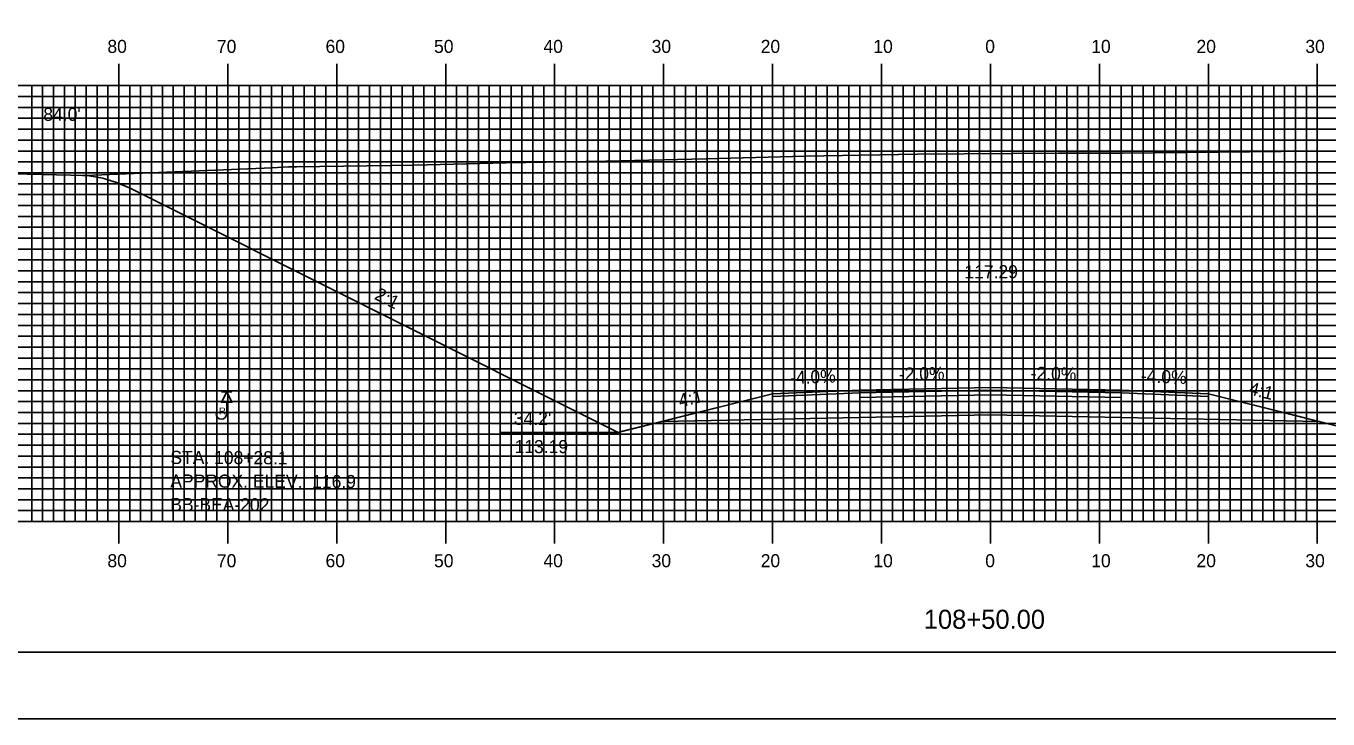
# Model space of a CAD drawing. Extents: x 1768874 to 1769217, y 442591 to 442811.
# Drawn here: x 1768951.5 to 1769071, y 442590.5 to 442654.1 of the extents above; entities that cross this region are included whole.
import ezdxf

# ---------------------------------------------------------------- set-up
doc = ezdxf.new("R2010")
doc.units = 0
for name, color, linetype in [('ANNOTATION', 7, 'Continuous'), ('BORDER', 7, 'Continuous'), ('BORING - REFUSAL', 7, 'Continuous'), ('D_Roadway_Centerline', 7, 'Continuous'), ('D_Roadway_Centerline_Text', 7, 'Continuous'), ('D_Roadway_Edge_Shoulder', 7, 'Continuous'), ('D_Roadway_Edge_TW', 7, 'Continuous'), ('D_Roadway_Pavement', 7, 'Continuous'), ('D_Roadway_SlopeLines', 7, 'Continuous'), ('D_Roadway_SubGrade', 7, 'Continuous'), ('D_Text_Standard', 7, 'Continuous'), ('H_V ANNOTATION', 7, 'Continuous'), ('MAJOR', 7, 'Continuous'), ('MINOR', 7, 'Continuous'), ('PDRAIN', 7, 'Continuous'), ('PLOT BOUNDARY', 7, 'Continuous'), ('S_Roadway_Centerline', 7, 'Continuous')]:
    doc.layers.add(name, color=color, linetype=linetype)

msp = doc.modelspace()

# ---------------------------------------------------------------- linework, layer by layer
at = {"layer": 'BORDER'}
msp.add_lwpolyline([(1768890.39, 442596.67), (1769210.39, 442596.67), (1769210.39, 442806.67), (1768890.39, 442806.67)], close=True, dxfattribs=at)
at = {"layer": 'BORING - REFUSAL'}
for p, q in [((1768970.37, 442620.57), (1768969.41, 442620.57)), ((1768969.89, 442619.61), (1768969.89, 442618.55))]:
    msp.add_line(p, q, dxfattribs=at)
msp.add_lwpolyline([(1768969.89, 442620.57), (1768970.37, 442619.61), (1768969.41, 442619.61)], close=True, dxfattribs=at)
msp.add_arc((1768969.4, 442618.55), 0.485, 180, 0, dxfattribs=at)
at = {"layer": 'D_Roadway_Centerline'}
msp.add_lwpolyline([(1768956.02, 442640.45), (1768957.27, 442640.39), (1768957.99, 442640.27), (1768958.52, 442640.17), (1768959.57, 442639.85), (1768959.77, 442639.79), (1768959.88, 442639.75), (1768961.02, 442639.25), (1768961.03, 442639.25), (1769005.82, 442616.85), (1769005.98, 442616.89), (1769009.81, 442617.85), (1769019.99, 442620.4), (1769027.99, 442620.72), (1769039.99, 442620.96), (1769051.99, 442620.72), (1769051.99, 442620.72), (1769051.99, 442620.72), (1769059.99, 442620.4), (1769059.99, 442620.4), (1769068.24, 442618.33), (1769070.16, 442617.85), (1769072.1, 442617.37)], dxfattribs=at)
at = {"layer": 'D_Roadway_Edge_Shoulder'}
for points in [[(1769027.99, 442620.72), (1769019.99, 442620.4), (1769019.99, 442620.15), (1769027.99, 442620.47)], [(1769051.99, 442620.72), (1769059.99, 442620.4), (1769059.99, 442620.15), (1769051.99, 442620.47)]]:
    msp.add_lwpolyline(points, close=True, dxfattribs=at)
at = {"layer": 'D_Roadway_Edge_TW'}
msp.add_lwpolyline([(1769027.99, 442620.47), (1769027.99, 442620.72), (1769039.99, 442620.96), (1769051.99, 442620.72), (1769051.99, 442620.47), (1769039.99, 442620.71)], close=True, dxfattribs=at)
at = {"layer": 'D_Roadway_Pavement'}
msp.add_lwpolyline([(1769027.99, 442620.05), (1769027.99, 442620.47), (1769039.99, 442620.71), (1769051.99, 442620.47), (1769051.99, 442620.05), (1769039.99, 442620.29)], close=True, dxfattribs=at)
at = {"layer": 'D_Roadway_SlopeLines'}
for points in [[(1769005.82, 442616.85), (1768961.02, 442639.25), (1768959.77, 442639.79), (1768958.52, 442640.17), (1768957.27, 442640.39), (1768956.02, 442640.45)], [(1769019.99, 442620.4), (1769005.82, 442616.85)], [(1769059.99, 442620.4), (1769074.16, 442616.85)]]:
    msp.add_lwpolyline(points, dxfattribs=at)
at = {"layer": 'D_Roadway_SubGrade'}
msp.add_lwpolyline([(1769027.99, 442618.22), (1769009.81, 442617.85), (1769019.99, 442620.4), (1769019.99, 442620.15), (1769027.99, 442620.47), (1769039.99, 442620.71), (1769051.99, 442620.47), (1769059.99, 442620.15), (1769059.99, 442620.4), (1769070.16, 442617.85), (1769051.99, 442618.22), (1769039.99, 442618.46)], close=True, dxfattribs=at)
at = {"layer": 'MAJOR'}
for p, q in [((1768959.99, 442650.67), (1768959.99, 442648.67)), ((1768969.99, 442650.67), (1768969.99, 442648.67)), ((1768979.99, 442650.67), (1768979.99, 442648.67)), ((1768989.99, 442650.67), (1768989.99, 442648.67)), ((1768999.99, 442650.67), (1768999.99, 442648.67)), ((1769009.99, 442650.67), (1769009.99, 442648.67)), ((1769019.99, 442650.67), (1769019.99, 442648.67)), ((1769029.99, 442650.67), (1769029.99, 442648.67)), ((1769039.99, 442650.67), (1769039.99, 442648.67)), ((1769049.99, 442650.67), (1769049.99, 442648.67)), ((1769059.99, 442650.67), (1769059.99, 442648.67)), ((1769069.99, 442650.67), (1769069.99, 442648.67)), ((1768899.99, 442648.67), (1769179.99, 442648.67)), ((1768899.99, 442648.67), (1769179.99, 442648.67)), ((1768959.99, 442608.67), (1768959.99, 442648.67)), ((1768969.99, 442608.67), (1768969.99, 442648.67)), ((1768979.99, 442608.67), (1768979.99, 442648.67)), ((1768989.99, 442608.67), (1768989.99, 442648.67)), ((1768999.99, 442608.67), (1768999.99, 442648.67)), ((1769009.99, 442608.67), (1769009.99, 442648.67)), ((1769019.99, 442608.67), (1769019.99, 442648.67)), ((1769029.99, 442608.67), (1769029.99, 442648.67)), ((1769039.99, 442608.67), (1769039.99, 442648.67)), ((1769049.99, 442608.67), (1769049.99, 442648.67)), ((1769059.99, 442608.67), (1769059.99, 442648.67)), ((1769069.99, 442608.67), (1769069.99, 442648.67)), ((1768899.99, 442643.67), (1769179.99, 442643.67)), ((1768899.99, 442638.67), (1769179.99, 442638.67)), ((1768899.99, 442633.67), (1769179.99, 442633.67)), ((1768899.99, 442628.67), (1769179.99, 442628.67)), ((1768899.99, 442623.67), (1769179.99, 442623.67)), ((1768899.99, 442618.67), (1769179.99, 442618.67)), ((1768899.99, 442613.67), (1769179.99, 442613.67)), ((1768899.99, 442608.67), (1769179.99, 442608.67)), ((1768899.99, 442608.67), (1769179.99, 442608.67)), ((1768959.99, 442606.66), (1768959.99, 442608.67)), ((1768969.99, 442606.66), (1768969.99, 442608.67)), ((1768979.99, 442606.66), (1768979.99, 442608.67)), ((1768989.99, 442606.66), (1768989.99, 442608.67)), ((1768999.99, 442606.66), (1768999.99, 442608.67)), ((1769009.99, 442606.66), (1769009.99, 442608.67)), ((1769019.99, 442606.66), (1769019.99, 442608.67)), ((1769029.99, 442606.66), (1769029.99, 442608.67)), ((1769039.99, 442606.66), (1769039.99, 442608.67)), ((1769049.99, 442606.66), (1769049.99, 442608.67)), ((1769059.99, 442606.66), (1769059.99, 442608.67)), ((1769069.99, 442606.66), (1769069.99, 442608.67))]:
    msp.add_line(p, q, dxfattribs=at)
at = {"layer": 'MINOR'}
for p, q in [((1768951.99, 442608.67), (1768951.99, 442648.67)), ((1768952.99, 442608.67), (1768952.99, 442648.67)), ((1768953.99, 442608.67), (1768953.99, 442648.67)), ((1768954.99, 442608.67), (1768954.99, 442648.67)), ((1768955.99, 442608.67), (1768955.99, 442648.67)), ((1768956.99, 442608.67), (1768956.99, 442648.67)), ((1768957.99, 442608.67), (1768957.99, 442648.67)), ((1768958.99, 442608.67), (1768958.99, 442648.67)), ((1768960.99, 442608.67), (1768960.99, 442648.67)), ((1768961.99, 442608.67), (1768961.99, 442648.67)), ((1768962.99, 442608.67), (1768962.99, 442648.67)), ((1768963.99, 442608.67), (1768963.99, 442648.67)), ((1768964.99, 442608.67), (1768964.99, 442648.67)), ((1768965.99, 442608.67), (1768965.99, 442648.67)), ((1768966.99, 442608.67), (1768966.99, 442648.67)), ((1768967.99, 442608.67), (1768967.99, 442648.67)), ((1768968.99, 442608.67), (1768968.99, 442648.67)), ((1768970.99, 442608.67), (1768970.99, 442648.67)), ((1768971.99, 442608.67), (1768971.99, 442648.67)), ((1768972.99, 442608.67), (1768972.99, 442648.67)), ((1768973.99, 442608.67), (1768973.99, 442648.67)), ((1768974.99, 442608.67), (1768974.99, 442648.67)), ((1768975.99, 442608.67), (1768975.99, 442648.67)), ((1768976.99, 442608.67), (1768976.99, 442648.67)), ((1768977.99, 442608.67), (1768977.99, 442648.67)), ((1768978.99, 442608.67), (1768978.99, 442648.67)), ((1768980.99, 442608.67), (1768980.99, 442648.67)), ((1768981.99, 442608.67), (1768981.99, 442648.67)), ((1768982.99, 442608.67), (1768982.99, 442648.67)), ((1768983.99, 442608.67), (1768983.99, 442648.67)), ((1768984.99, 442608.67), (1768984.99, 442648.67)), ((1768985.99, 442608.67), (1768985.99, 442648.67)), ((1768986.99, 442608.67), (1768986.99, 442648.67)), ((1768987.99, 442608.67), (1768987.99, 442648.67)), ((1768988.99, 442608.67), (1768988.99, 442648.67)), ((1768990.99, 442608.67), (1768990.99, 442648.67)), ((1768991.99, 442608.67), (1768991.99, 442648.67)), ((1768992.99, 442608.67), (1768992.99, 442648.67)), ((1768993.99, 442608.67), (1768993.99, 442648.67)), ((1768994.99, 442608.67), (1768994.99, 442648.67)), ((1768995.99, 442608.67), (1768995.99, 442648.67)), ((1768996.99, 442608.67), (1768996.99, 442648.67)), ((1768997.99, 442608.67), (1768997.99, 442648.67)), ((1768998.99, 442608.67), (1768998.99, 442648.67)), ((1769000.99, 442608.67), (1769000.99, 442648.67)), ((1769001.99, 442608.67), (1769001.99, 442648.67)), ((1769002.99, 442608.67), (1769002.99, 442648.67)), ((1769003.99, 442608.67), (1769003.99, 442648.67)), ((1769004.99, 442608.67), (1769004.99, 442648.67)), ((1769005.99, 442608.67), (1769005.99, 442648.67)), ((1769006.99, 442608.67), (1769006.99, 442648.67)), ((1769007.99, 442608.67), (1769007.99, 442648.67)), ((1769008.99, 442608.67), (1769008.99, 442648.67)), ((1769010.99, 442608.67), (1769010.99, 442648.67)), ((1769011.99, 442608.67), (1769011.99, 442648.67)), ((1769012.99, 442608.67), (1769012.99, 442648.67)), ((1769013.99, 442608.67), (1769013.99, 442648.67)), ((1769014.99, 442608.67), (1769014.99, 442648.67)), ((1769015.99, 442608.67), (1769015.99, 442648.67)), ((1769016.99, 442608.67), (1769016.99, 442648.67)), ((1769017.99, 442608.67), (1769017.99, 442648.67)), ((1769018.99, 442608.67), (1769018.99, 442648.67)), ((1769020.99, 442608.67), (1769020.99, 442648.67)), ((1769021.99, 442608.67), (1769021.99, 442648.67)), ((1769022.99, 442608.67), (1769022.99, 442648.67)), ((1769023.99, 442608.67), (1769023.99, 442648.67)), ((1769024.99, 442608.67), (1769024.99, 442648.67)), ((1769025.99, 442608.67), (1769025.99, 442648.67)), ((1769026.99, 442608.67), (1769026.99, 442648.67)), ((1769027.99, 442608.67), (1769027.99, 442648.67)), ((1769028.99, 442608.67), (1769028.99, 442648.67)), ((1769030.99, 442608.67), (1769030.99, 442648.67)), ((1769031.99, 442608.67), (1769031.99, 442648.67)), ((1769032.99, 442608.67), (1769032.99, 442648.67)), ((1769033.99, 442608.67), (1769033.99, 442648.67)), ((1769034.99, 442608.67), (1769034.99, 442648.67)), ((1769035.99, 442608.67), (1769035.99, 442648.67)), ((1769036.99, 442608.67), (1769036.99, 442648.67)), ((1769037.99, 442608.67), (1769037.99, 442648.67)), ((1769038.99, 442608.67), (1769038.99, 442648.67)), ((1769040.99, 442608.67), (1769040.99, 442648.67)), ((1769041.99, 442608.67), (1769041.99, 442648.67)), ((1769042.99, 442608.67), (1769042.99, 442648.67)), ((1769043.99, 442608.67), (1769043.99, 442648.67)), ((1769044.99, 442608.67), (1769044.99, 442648.67)), ((1769045.99, 442608.67), (1769045.99, 442648.67)), ((1769046.99, 442608.67), (1769046.99, 442648.67)), ((1769047.99, 442608.67), (1769047.99, 442648.67)), ((1769048.99, 442608.67), (1769048.99, 442648.67)), ((1769050.99, 442608.67), (1769050.99, 442648.67)), ((1769051.99, 442608.67), (1769051.99, 442648.67)), ((1769052.99, 442608.67), (1769052.99, 442648.67)), ((1769053.99, 442608.67), (1769053.99, 442648.67)), ((1769054.99, 442608.67), (1769054.99, 442648.67)), ((1769055.99, 442608.67), (1769055.99, 442648.67)), ((1769056.99, 442608.67), (1769056.99, 442648.67)), ((1769057.99, 442608.67), (1769057.99, 442648.67)), ((1769058.99, 442608.67), (1769058.99, 442648.67)), ((1769060.99, 442608.67), (1769060.99, 442648.67)), ((1769061.99, 442608.67), (1769061.99, 442648.67)), ((1769062.99, 442608.67), (1769062.99, 442648.67)), ((1769063.99, 442608.67), (1769063.99, 442648.67)), ((1769064.99, 442608.67), (1769064.99, 442648.67)), ((1769065.99, 442608.67), (1769065.99, 442648.67)), ((1769066.99, 442608.67), (1769066.99, 442648.67)), ((1769067.99, 442608.67), (1769067.99, 442648.67)), ((1769068.99, 442608.67), (1769068.99, 442648.67)), ((1768899.99, 442647.67), (1769179.99, 442647.67)), ((1768899.99, 442646.67), (1769179.99, 442646.67)), ((1768899.99, 442645.67), (1769179.99, 442645.67)), ((1768899.99, 442644.67), (1769179.99, 442644.67)), ((1768899.99, 442642.67), (1769179.99, 442642.67)), ((1768899.99, 442641.67), (1769179.99, 442641.67)), ((1768899.99, 442640.67), (1769179.99, 442640.67)), ((1768899.99, 442639.67), (1769179.99, 442639.67)), ((1768899.99, 442637.67), (1769179.99, 442637.67)), ((1768899.99, 442636.67), (1769179.99, 442636.67)), ((1768899.99, 442635.67), (1769179.99, 442635.67)), ((1768899.99, 442634.67), (1769179.99, 442634.67)), ((1768899.99, 442632.67), (1769179.99, 442632.67)), ((1768899.99, 442631.67), (1769179.99, 442631.67)), ((1768899.99, 442630.67), (1769179.99, 442630.67)), ((1768899.99, 442629.67), (1769179.99, 442629.67)), ((1768899.99, 442627.67), (1769179.99, 442627.67)), ((1768899.99, 442626.67), (1769179.99, 442626.67)), ((1768899.99, 442625.67), (1769179.99, 442625.67)), ((1768899.99, 442624.67), (1769179.99, 442624.67)), ((1768899.99, 442622.67), (1769179.99, 442622.67)), ((1768899.99, 442621.67), (1769179.99, 442621.67)), ((1768899.99, 442620.67), (1769179.99, 442620.67)), ((1768899.99, 442619.67), (1769179.99, 442619.67)), ((1768899.99, 442617.67), (1769179.99, 442617.67)), ((1768899.99, 442616.67), (1769179.99, 442616.67)), ((1768899.99, 442615.67), (1769179.99, 442615.67)), ((1768899.99, 442614.67), (1769179.99, 442614.67)), ((1768899.99, 442612.67), (1769179.99, 442612.67)), ((1768899.99, 442611.67), (1769179.99, 442611.67)), ((1768899.99, 442610.67), (1769179.99, 442610.67)), ((1768899.99, 442609.67), (1769179.99, 442609.67))]:
    msp.add_line(p, q, dxfattribs=at)
at = {"layer": 'PDRAIN'}
msp.add_line((1768995.09, 442616.85), (1769005.82, 442616.85), dxfattribs=at)
at = {"layer": 'PLOT BOUNDARY'}
msp.add_lwpolyline([(1768874.2, 442590.55), (1769214.2, 442590.55), (1769214.2, 442810.55), (1768874.2, 442810.55)], close=True, dxfattribs=at)
at = {"layer": 'S_Roadway_Centerline'}
msp.add_lwpolyline([(1768899.99, 442641.68), (1768914.87, 442641.42), (1768918.51, 442641.37), (1768929.92, 442641.03), (1768938.61, 442640.84), (1768939.42, 442640.83), (1768942.2, 442640.75), (1768956.92, 442640.43), (1768974.05, 442641.14), (1768975.57, 442641.23), (1768976.29, 442641.22), (1768987.05, 442641.38), (1768995.55, 442641.59), (1769004.68, 442641.73), (1769013.89, 442641.95), (1769022.99, 442642.2), (1769033.25, 442642.37), (1769046.24, 442642.48), (1769052.18, 442642.48), (1769057.97, 442642.53), (1769069.58, 442642.66), (1769071.5, 442642.66)], dxfattribs=at)

# ---------------------------------------------------------------- texts
at = {"layer": 'ANNOTATION'}
for s, rotation, p in [('2:1', 333.4345, (1768983.36, 442629.12)), ('-4.0%', 2.2905, (1769021.62, 442621.26)), ('-2.0%', 1.1458, (1769031.59, 442621.59)), ('-2.0%', 358.8542, (1769043.67, 442621.68)), ('-4.0%', 357.7095, (1769053.78, 442621.45)), ('4:1', 14.0389, (1769011.52, 442619.14)), ('4:1', 345.9616, (1769063.62, 442620.35))]:
    msp.add_text(s, height=1.2, rotation=rotation, dxfattribs=at).set_placement(p)
for s, p in [("34.2'", (1768996.25, 442617.54)), ('113.19', (1768996.31, 442614.94))]:
    msp.add_text(s, height=1.2, dxfattribs=at).set_placement(p)
at = {"layer": 'BORING - REFUSAL'}
msp.add_text('R', height=0.64, dxfattribs=at).set_placement((1768969.18, 442618.49))
for s, p in [('STA. 108+28.1', (1768964.72, 442613.95)), ('APPROX. ELEV.  116.9', (1768964.71, 442611.79)), ('BB-BEA-202', (1768964.71, 442609.63))]:
    msp.add_text(s, height=1.2, rotation=359.8142, dxfattribs=at).set_placement(p)
at = {"layer": 'D_Roadway_Centerline'}
for s, p in [('C', (1769039.98, 442620.96)), ('L', (1769039.99, 442620.95))]:
    msp.add_text(s, height=0.0146, dxfattribs=at).set_placement(p)
at = {"layer": 'D_Roadway_Centerline_Text'}
msp.add_text('117.29', height=1.2, dxfattribs=at).set_placement((1769037.6, 442630.99))
at = {"layer": 'D_Text_Standard'}
msp.add_text("84.0'", height=1.2, dxfattribs=at).set_placement((1768953.06, 442645.44))
at = {"layer": 'H_V ANNOTATION'}
for s, height, p in [('80', 1.2, (1768958.94, 442651.67)), ('70', 1.2, (1768968.99, 442651.67)), ('60', 1.2, (1768978.96, 442651.67)), ('50', 1.2, (1768988.92, 442651.67)), ('40', 1.2, (1768998.96, 442651.67)), ('30', 1.2, (1769008.89, 442651.67)), ('20', 1.2, (1769018.9, 442651.67)), ('10', 1.2, (1769029.24, 442651.67)), ('0', 1.2, (1769039.51, 442651.67)), ('10', 1.2, (1769049.24, 442651.67)), ('20', 1.2, (1769058.9, 442651.67)), ('30', 1.2, (1769068.89, 442651.67)), ('80', 1.2, (1768958.94, 442604.47)), ('70', 1.2, (1768968.99, 442604.47)), ('60', 1.2, (1768978.96, 442604.47)), ('50', 1.2, (1768988.92, 442604.47)), ('40', 1.2, (1768998.96, 442604.47)), ('30', 1.2, (1769008.89, 442604.47)), ('20', 1.2, (1769018.9, 442604.47)), ('10', 1.2, (1769029.24, 442604.47)), ('0', 1.2, (1769039.51, 442604.47)), ('10', 1.2, (1769049.24, 442604.47)), ('20', 1.2, (1769058.9, 442604.47)), ('30', 1.2, (1769068.89, 442604.47)), ('108+50.00', 1.75, (1769033.87, 442598.82))]:
    msp.add_text(s, height=height, dxfattribs=at).set_placement(p)

doc.saveas('drawing.dxf')
